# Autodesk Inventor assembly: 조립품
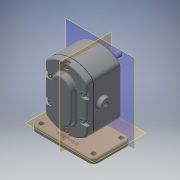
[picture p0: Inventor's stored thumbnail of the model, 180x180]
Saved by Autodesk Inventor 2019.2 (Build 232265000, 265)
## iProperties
Created: 2019-03
Part Number: 조립품
Material: 일반
Document SubType Name: Assembly
Designer: User
Author: User
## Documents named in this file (11)
- C:\Users\User\Desktop\490307V1023\조립품.iam
- C:\Users\User\Desktop\490307V1023\개스킷.ipt
- C:\Users\User\Desktop\490307V1023\메인축.ipt
- C:\Users\User\Desktop\490307V1023\베어링부시.ipt
- C:\Users\User\Desktop\490307V1023\본체.ipt
- C:\Users\User\Desktop\490307V1023\볼트 M5.ipt
- C:\Users\User\Desktop\490307V1023\서브축.ipt
- C:\Users\User\Desktop\490307V1023\스퍼기어.ipt
- C:\Users\User\Desktop\490307V1023\오일 실 16 28 7.ipt
- C:\Users\User\Desktop\490307V1023\커버.ipt
- C:\Users\User\Desktop\490307V1023\키 6 x 6 x 18.ipt
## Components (1 placed, 1 different names)
1. 개스킷:1
